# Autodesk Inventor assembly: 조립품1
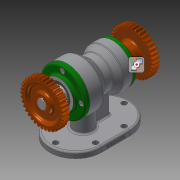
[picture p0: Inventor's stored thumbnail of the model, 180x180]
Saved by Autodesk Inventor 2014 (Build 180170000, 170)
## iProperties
Created: 2020-01
Part Number: 조립품1
Document SubType Name: Assembly
Designer: kh
Author: kh
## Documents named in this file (13)
- D:\700104V1024\조립품1.iam
- D:\700104V1024\본체.ipt
- D:\700104V1024\Ű 5 x 5 x 18.ipt
- D:\700104V1024\베어링 6203.ipt
- D:\700104V1024\축.ipt
- D:\700104V1024\앞커버.ipt
- D:\700104V1024\뒤커버.ipt
- D:\700104V1024\베어링 6205.ipt
- D:\700104V1024\볼트 M4.ipt
- D:\700104V1024\오일 실 25 38 8.ipt
- D:\700104V1024\오일 실 17 30 8.ipt
- D:\700104V1024\스퍼기어.ipt
- D:\700104V1024\멈춤나사 M3.ipt
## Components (2 placed, 1 different names)
1. Ű 5 x 5 x 18:1 — 각도:1
2. Ű 5 x 5 x 18:2
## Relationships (1: Angle 1)
- 각도:1 [Angle]: Ű 5 x 5 x 18:1
